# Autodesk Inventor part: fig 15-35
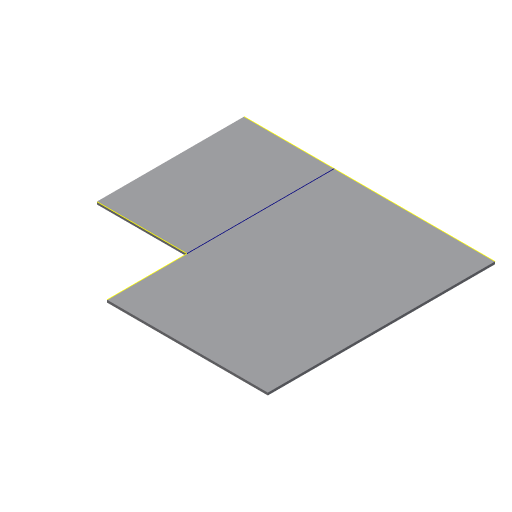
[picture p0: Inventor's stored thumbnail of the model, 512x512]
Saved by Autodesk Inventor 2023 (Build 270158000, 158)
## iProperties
Created: 2005-03
Part Number: fig 15-35
Document SubType Name: Sheet Metal
Designer: CADCIM
Manufacturer: Standard
Standards Organization: Custom
Density: 1 g/cm^3
Sheet Metal Rule: Default
Material: Generic
Appearance: Default
Author: CADCIM
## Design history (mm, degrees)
node "Face1"
  sketch "Sketch1"
    geometry: L1 (31.393, 35.714)-(-19.875, 35.714); L2 (-19.875, 35.714)-(-19.875, 5.625); L3 (-19.875, 5.625)-(-1.5, 5.625); L4 (-1.5, 5.625)-(-1.5, -10.705); L5 (-1.5, -10.705)-(31.393, -10.705); L6 (31.393, -10.705)-(31.393, 35.714)
    constraints: 12 end point, 4 parallel, 1 horizontal, 1 perpendicular
sketch "Sketch3"
  geometry: L1 (18.375, -30.089)-(18.375, 0); L2 (18.375, -46.42)-(18.375, -30.089) reference; L3 (18.375, -30.089)-(0, -30.089) reference; L4 (0, 0)-(51.268, 0) reference
  constraints: 3 point on line, 2 end point, 1 vertical
body "Solid1"
face "Plate1" dims "d1" = 0.5 (= Thickness)
other parameters: "Thickness" = 0.5, "BendRadius" = 0.5 (= Thickness), "BendReliefWidth" = 0.5 (= Thickness), "BendReliefDepth" = 0.25 (= 0.5 x Thickness), "CornerReliefSize" = 2 (= 4 x Thickness), "SeamGap" = 0.01, "MinimumRemnant" = 1 (= 2 x Thickness), "TransitionRadius" = 0.5 (= BendRadius), "d0" = 0.5 (= BendRadius), "JacobiRadiusSize" = 0.5 (= Thickness), "GapSize" = 0.5 (= Thickness)
